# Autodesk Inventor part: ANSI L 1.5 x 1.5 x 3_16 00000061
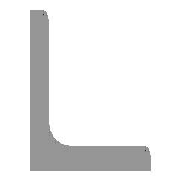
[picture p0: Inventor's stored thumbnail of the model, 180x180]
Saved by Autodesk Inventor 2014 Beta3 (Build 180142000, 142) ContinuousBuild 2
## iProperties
_CCFamilyMember: 5
_CCFamilyDisplayName: ANSI L (Equal angles) - Angle Steel
_FrameMemberDoc: Frame Member File
_Version: 15.0.0
_GetPNFromCC: 1
Created: 2010-11
Part Number: ANSI L 1.5 x 1.5 x 3_16 00000061
Material: Steel, Mild
Description: Angle Steel
Document SubType Name: Modeling
Standard: ANSI
Designer: Beta-8540w
Standards Organization: ANSI
Language: en-US
Size Designation: L 1.5 x 1.5 x 3/16
Categories: <MemberInstance><Categories><Category DisplayName="Structural Shapes" InternalName="089c4875-fa83-4c05-b084-43b9cc11f5ed" Mnemonic="GRDR"><CategoryParameter Dis
Stock Number: L 1.5 x 1.5 x 3/16
Density: 7.86 g/cm^3
Appearance: Steel
IsCustomPart: 1
G_L: 31.773 in
G_W: 1.500 in
G_H: 1.500 in
+D492D07F-02B9-496C-B776-82EB711B3C50+CUTDETAIL1: Cut
Author: Beta-8540w
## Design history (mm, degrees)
node "Start plane"
node "End plane"
sketch "Sketch"
  geometry: L1 (38.1, 0)-(0, 0); L2 (0, 0)-(0, 38.1); L3 (0, 38.1)-(2.476, 38.1); L4 (4.762, 35.814)-(4.762, 9.589); L5 (9.588, 4.763)-(35.814, 4.763); L6 (38.1, 2.477)-(38.1, 0); L7 (0, -11.041)-(0, 31.538); L8 (-11.041, 0)-(31.538, 0); L9 (0, 48.496)-(0, -20.964) reference; L10 (-20.964, 0)-(48.496, 0) reference; A1 r 4.826 centre (9.588, 9.589) between (4.762, 9.589) and (9.588, 4.763); A2 r 2.286 centre (2.476, 35.814) between (4.762, 35.814) and (2.476, 38.1); A3 r 2.286 centre (35.814, 2.477) between (38.1, 2.477) and (35.814, 4.763); 3 further points
  constraints: 16 end point, 6 point on circle, 6 point on line, 6 tangent, 4 parallel, 3 centre point, 2 collinear, 1 equal radius, 1 horizontal, 1 perpendicular
  dimensions: "d0" = 38.1 distance between parallel lines of L6 L2 (= G_H); "d1" = 38.1 distance between parallel lines of L3 L1 (= G_H); "d2" = 4.7625 distance between parallel lines of L2 L4 (= G_T); "d3" = 4.7625 distance between parallel lines of L1 L5 (= G_T); "d10" = 0 distance between parallel lines of L7 L2 (computed from ex); "d11" = 0 distance between parallel lines of L8 L1 (computed from d10); "d14" = 4.826 radius of A1 (= G_IR); "d15" = 2.286 radius of A2 (= G_ER)
extrude "Body" new body sketch "Sketch" stored distance "d4" = 807.0404 (= G_L); taper "d5" = 0 deg
node "Driven Length"
  sketch "Sketch3"
    geometry: L1 (0, 0)-(10, 0) reference
    constraints: 2 end point, 1 horizontal
  workplane "Work Plane3"
  sketch "Sketch4"
    geometry: L1 (-2, 0)-(12, 0) reference; L2 (-2, 807.04)-(12, 807.04) reference
    dimensions: "d17" = 807.0404 distance between parallel lines of L1 L2 (derived)
workplane "Work Plane4"
split "Split1"
body "Solid1"
other parameters: "G_H" = 38.1 [user parameter; used in 2 equation terms], "G_T" = 4.7625 [user parameter; used in 2 equation terms], "G_ER" = 2.286 [user parameter; used in 1 equation term], "G_IR" = 4.826 [user parameter; used in 1 equation term], "G_L" = 807.0404 (= d17) [user parameter; used in 1 equation term], "ex" = 0 [user parameter; used in 1 equation term], "G_OFFSET_START" = 0 [user parameter; used in 1 equation term], "G_OFFSET_END" = -29.72503 [user parameter; used in 1 equation term], "d12" = 0 (computed from G_OFFSET_START), "d13" = 807.0404 (= G_OFFSET_END + B_L), "B_L" = 836.76542 [user parameter; used in 1 equation term], "d16" = 90 deg, "MAS" = 0.26787 [user parameter]
